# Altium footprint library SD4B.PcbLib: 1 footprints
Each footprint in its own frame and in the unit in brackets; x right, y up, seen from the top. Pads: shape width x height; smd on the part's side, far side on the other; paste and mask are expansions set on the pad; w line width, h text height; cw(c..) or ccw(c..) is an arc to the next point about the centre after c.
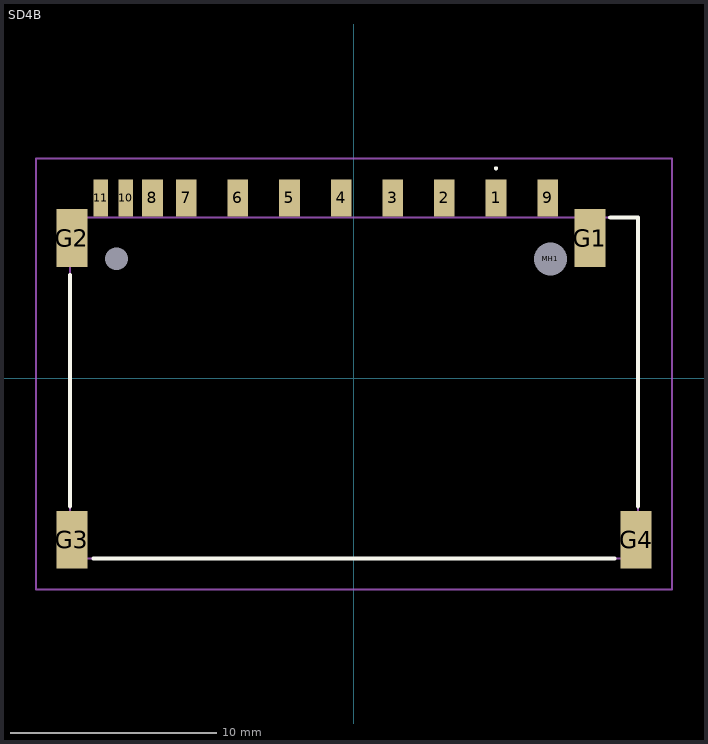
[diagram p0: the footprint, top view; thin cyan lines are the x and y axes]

## SD4B [mm]
pads (17):
  rect 1x1.8 smd: 1(6.875,8.725) 2(4.375,8.725) 3(1.875,8.725) 4(-0.625,8.725) 5(-3.125,8.725) 6(-5.625,8.725) 7(-8.125,8.725) 8(-9.755,8.725) 9(9.375,8.725)
  rect 0.7x1.8 smd: 10(-11.055,8.725) 11(-12.255,8.725)
  rect 1.5x2.8 smd: G1(11.42,6.775) G2(-13.65,6.775) G3(-13.65,-7.825) G4(13.65,-7.825)
  round 0.8 hole 1.6 unplated: MH1(9.5,5.775)
  round 0.55 hole 1.1 unplated: MH2(-11.5,5.775)
Top Overlay:
  lines w0.1: 6.875,10.1 cw(c6.875,10.15) 6.875,10.2 ; 6.875,10.1 6.875,10.1 ; 6.875,10.1 ccw(c6.875,10.15) 6.875,10.2 ; 6.875,10.2 6.875,10.2
  lines w0.2: -13.75,-6.2 -13.75,5 ; -12.6,-8.725 12.6,-8.725 ; 12.4,7.775 13.75,7.775 13.75,-6.2
Mechanical 15:
  lines w0.1: -13.75,-8.725 13.75,-8.725 13.75,7.775 -13.75,7.775 -13.75,-8.725
Mechanical 20:
  lines w0.1: -15.4,-10.225 15.4,-10.225 15.4,10.625 -15.4,10.625 -15.4,-10.225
